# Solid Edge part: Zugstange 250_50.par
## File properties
Username: ahadarics
Dokumentum tartalom típus: 0
Author: ahadarics
Last saved by: ahadarics
Revision: 79
Sűrűség: 0,000 kg/m^3
Pontosság: 0,990
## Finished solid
Body 1: solid body, 5 faces, 7 edges, 4 vertices.
  Faces by surface: cone 2, plane 2, cylinder 1
  Edges by curve: circle 5, line 2
Bounding box of the edges (mm): 20.000 x 20.000 x 198.000, from (-10, -10, -111.5) to (10, 10, 86.5).
Cylindrical faces by radius (mm): R10 x1
Conical faces (half-angle, radius in mm at the cone's reference point): 45 deg R9.25 x2
Planar faces by outward normal: +z 1, -z 1
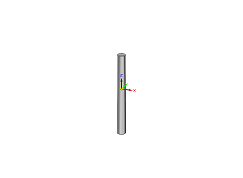
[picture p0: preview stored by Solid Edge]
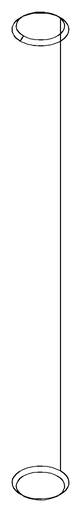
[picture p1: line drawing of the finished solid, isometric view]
